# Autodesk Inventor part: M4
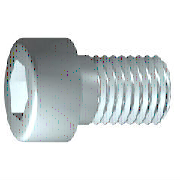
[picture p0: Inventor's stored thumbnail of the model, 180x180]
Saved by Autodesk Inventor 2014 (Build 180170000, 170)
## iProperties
IsCustomPart: 0
Created: 2016-04
Part Number: M4
Material: 강철, 연강
Description: 6각머리 태핑 나사
Document SubType Name: Modeling
Standard: KS B 1003
Designer: mdu
Standards Organization: KS
Language: ko-KR
Size Designation: M 4 x 10
Categories: <MemberInstance><Categories><Category DisplayName="조임쇠" InternalName="e4da775c-781d-43d5-af7c-5136215cf5a6" Mnemonic="FSTN"><Category DisplayName="볼트" InternalN
Density: 7.86 g/cm^3
Mass: 2.0371 g
Surface Area: 3.0572 cm^2
Volume: 0.259174 cm^3
Appearance: Metal 1800F Hot
Author: mdu
Revision Number: 1
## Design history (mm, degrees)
sketch "스케치1"
  geometry: L1 (-1, 0)-(10, 0); L2 (10, 0)-(10, 2); L3 (10, 2)-(1.75, 2); L4 (1.75, 2)-(1.32, 2); L5 (1.32, 2)-(0, 2); L6 (0, 2)-(0, 3.5); L7 (0, 3.5)-(-4, 3.5); L8 (-4, 3.5)-(-4, 1.732); L9 (-4, 1.732)-(-2, 1.732); L10 (-2, 1.732)-(-1, 0); L11 (-6.8, 0)-(12.8, 0) reference; L12 (0, -0.7)-(0, 4.2) reference; L13 (1.75, 2)-(0, 2)
  constraints: 22 end point, 6 parallel, 2 collinear, 2 perpendicular, 1 horizontal, 1 point on line
  dimensions: "d1" = 8.25 distance from line of L3.end L2 (= GEL); "d2" = 0.42952 distance of L4.end L3.end (computed from GAL); "d3" = 4 distance between parallel lines of L8 L6 (= KOH); "d4" = 2 distance of L8.end L9.end (= INTI); "d5" = 60 deg angle of L10 L1; "d6" = 4 diameter of L3 L1 (= GD); "d7" = 4 diameter of L5 L1 (= BDM); "d8" = 3.4641 diameter of L9 L1 (= 1.1547 x SW); "d9" = 7 diameter of L7 L1 (= KOD); "d26" = 10 distance between parallel lines of L12 L2 (= NLG)
revolve "본체" sketch "스케치1" stored, may be unused: angle "d10" = 90 deg
sketch "스케치2"
  geometry: L1 (0, -4.9)-(0, 4.9) reference; L2 (-4.9, 0)-(4.9, 0) reference; L3 (1.732, 0)-(0.866, -1.5); L4 (0.866, -1.5)-(-0.866, -1.5); L5 (-0.866, -1.5)-(-1.732, 0); L6 (-1.732, 0)-(-0.866, 1.5); L7 (-0.866, 1.5)-(0.866, 1.5); L8 (0.866, 1.5)-(1.732, 0); 2 further points
  constraints: 12 end point, 1 coincident, 1 horizontal alignment, 1 point on line, 12 other
extrude "슬롯" join sketch "스케치2" stored distance "d11" = 10; taper "d12" = 0 deg
workplane "Work Plane1"
fillet "Fillet2" dims "d30" = 0.1 (= R)
body "Solid1"
fillet "모깎기1" dims "d17" = 0.4 (= RR)
feature "스레드" dims "d13" = 8.25 (= GEL), "d14" = 0
chamfer "모따기1" distance "d15" = 0.42941 (= -0.5 x SPD + 0.5 x GD); stored, may be unused: second distance "d16" = 0.42941 (= GUL), angle "d27" = 45 deg
other parameters: "GD" = 4 (= NND) [user parameter; used in 2 equation terms], "NLG" = 10 [user parameter; used in 1 equation term], "GEL" = 8.25 [user parameter; used in 2 equation terms], "KOD" = 7 [user parameter; used in 1 equation term], "KOH" = 4 [user parameter; used in 1 equation term], "INTI" = 2 [user parameter; used in 1 equation term], "GAL" = 0.42941 (= 0.61345 x PTC) [user parameter; used in 1 equation term], "GUL" = 0.42941 (= 0.61345 x PTC) [user parameter; used in 1 equation term], "BDM" = 4 (= NND) [user parameter; used in 1 equation term], "SW" = 3 [user parameter; used in 2 equation terms], "RR" = 0.4 [user parameter; used in 1 equation term], "SPD" = 3.14117 (= NND - 1.2269 x PTC) [user parameter; used in 1 equation term], "d19" = 0, "d28" = 0, "d29" = 0, "R" = 0.1 [user parameter; used in 1 equation term], "PHH" = 0.2 [user parameter], "GD1" = 3.14117 (= THREADDIA - 1.2269 x PTC) [user parameter], "THREADDIA" = 4 [user parameter; used in 1 equation term], "FAWI" = 45 deg [user parameter], "TPU" = 14.28571 (computed from PTC) [user parameter], "PTC" = 0.7 [user parameter; used in 5 equation terms], "NND" = 4 [user parameter; used in 3 equation terms], "TOA" = 30 deg [user parameter], "E0" = 3.465 (= 1.155 x SW) [user parameter]
